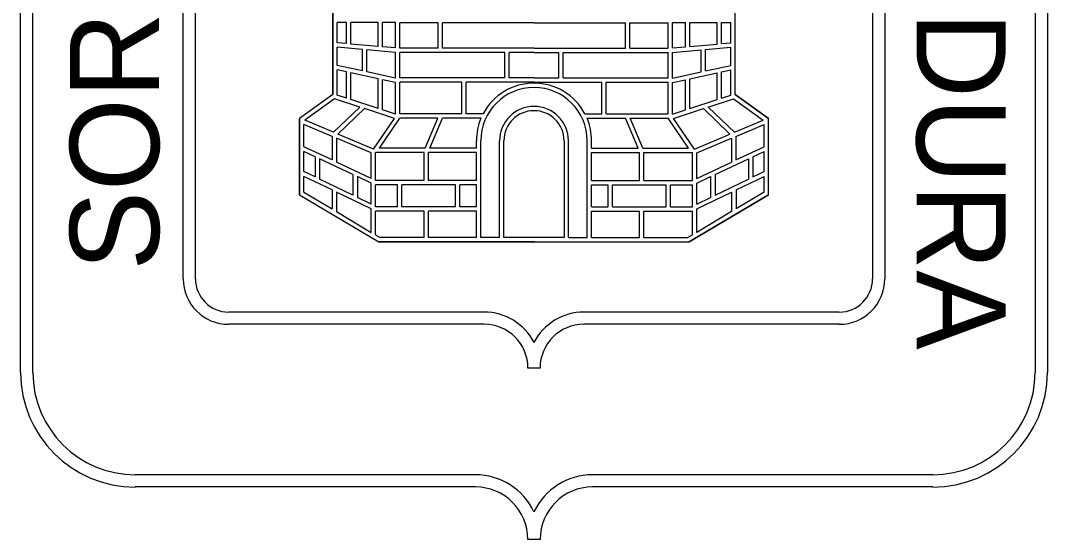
# Model space of a CAD drawing. Extents: x 0.2 to 61.3, y -17.9 to -0.8.
# Drawn here: x 50 to 60, y -17.88 to -12.82 of the extents above; entities that cross this region are included whole.
import ezdxf

# ---------------------------------------------------------------- set-up
doc = ezdxf.new("R2010")
doc.units = 0
doc.layers.add('Nivel 1', color=7, linetype='Continuous')
doc.layers.add('texto', color=7, linetype='Continuous')

msp = doc.modelspace()

# ---------------------------------------------------------------- linework, layer by layer
at = {"layer": 'Nivel 1'}
for p, q in [((50.003, -16.25), (50.003, -5.551)), ((60.003, -5.551), (60.003, -16.25)), ((50.122, -16.25), (50.122, -5.67)), ((59.884, -5.67), (59.884, -16.25)), ((51.587, -15.338), (51.587, -7.135)), ((58.419, -7.135), (58.419, -15.338)), ((51.706, -15.338), (51.706, -7.254)), ((58.3, -7.254), (58.3, -15.338)), ((53.044, -13.544), (53.044, -11.965)), ((56.962, -13.544), (56.962, -11.965)), ((53.178, -12.844), (53.087, -12.844)), ((53.087, -13.04), (53.087, -12.844)), ((53.178, -13.048), (53.178, -12.844)), ((53.485, -12.844), (53.22, -12.844)), ((53.22, -13.052), (53.22, -12.844)), ((53.485, -13.075), (53.485, -12.844)), ((53.655, -12.844), (53.528, -12.844)), ((53.528, -13.079), (53.528, -12.844)), ((53.655, -13.09), (53.655, -12.844)), ((54.07, -12.846), (53.697, -12.846)), ((53.697, -13.093), (53.697, -12.846)), ((54.07, -13.093), (54.07, -12.846)), ((55.003, -12.846), (54.113, -12.846)), ((54.113, -13.093), (54.113, -12.846)), ((55.003, -12.846), (55.893, -12.846)), ((55.893, -13.093), (55.893, -12.846)), ((55.935, -12.846), (56.309, -12.846)), ((55.935, -13.093), (55.935, -12.846)), ((56.309, -13.093), (56.309, -12.846)), ((56.351, -13.09), (56.351, -12.844)), ((56.351, -12.844), (56.478, -12.844)), ((56.478, -13.079), (56.478, -12.844)), ((56.521, -13.075), (56.521, -12.844)), ((56.521, -12.844), (56.785, -12.844)), ((56.785, -13.052), (56.785, -12.844)), ((56.828, -12.844), (56.919, -12.844)), ((56.828, -13.048), (56.828, -12.844)), ((56.919, -13.04), (56.919, -12.844)), ((53.178, -13.048), (53.087, -13.04)), ((53.087, -13.26), (53.087, -13.082)), ((53.334, -13.104), (53.087, -13.082)), ((53.485, -13.075), (53.22, -13.052)), ((53.655, -13.09), (53.528, -13.079)), ((54.07, -13.093), (53.697, -13.093)), ((55.003, -13.093), (54.113, -13.093)), ((55.003, -13.093), (55.893, -13.093)), ((55.935, -13.093), (56.309, -13.093)), ((56.351, -13.09), (56.478, -13.079)), ((56.521, -13.075), (56.785, -13.052)), ((56.672, -13.104), (56.919, -13.082)), ((56.828, -13.048), (56.919, -13.04)), ((56.919, -13.26), (56.919, -13.082)), ((53.334, -13.314), (53.334, -13.104)), ((53.376, -13.323), (53.376, -13.108)), ((53.655, -13.133), (53.376, -13.108)), ((53.655, -13.384), (53.655, -13.133)), ((54.719, -13.136), (53.697, -13.136)), ((53.697, -13.38), (53.697, -13.136)), ((54.719, -13.38), (54.719, -13.136)), ((55.003, -13.136), (54.761, -13.136)), ((54.761, -13.38), (54.761, -13.136)), ((55.003, -13.136), (55.245, -13.136)), ((55.245, -13.38), (55.245, -13.136)), ((55.287, -13.136), (56.309, -13.136)), ((55.287, -13.38), (55.287, -13.136)), ((56.309, -13.38), (56.309, -13.136)), ((56.351, -13.133), (56.63, -13.108)), ((56.351, -13.384), (56.351, -13.133)), ((56.63, -13.323), (56.63, -13.108)), ((56.672, -13.314), (56.672, -13.104)), ((53.334, -13.314), (53.087, -13.26)), ((56.672, -13.314), (56.919, -13.26)), ((53.178, -13.324), (53.087, -13.304)), ((53.087, -13.549), (53.087, -13.304)), ((53.178, -13.579), (53.178, -13.324)), ((53.485, -13.391), (53.22, -13.333)), ((53.22, -13.593), (53.22, -13.333)), ((53.655, -13.384), (53.376, -13.323)), ((53.485, -13.68), (53.485, -13.391)), ((53.655, -13.427), (53.528, -13.4)), ((53.528, -13.694), (53.528, -13.4)), ((54.719, -13.38), (53.697, -13.38)), ((55.003, -13.38), (54.761, -13.38)), ((55.003, -13.38), (55.245, -13.38)), ((55.287, -13.38), (56.309, -13.38)), ((56.351, -13.384), (56.63, -13.323)), ((56.351, -13.427), (56.478, -13.4)), ((56.478, -13.694), (56.478, -13.4)), ((56.521, -13.391), (56.785, -13.333)), ((56.521, -13.68), (56.521, -13.391)), ((56.785, -13.593), (56.785, -13.333)), ((56.828, -13.324), (56.919, -13.304)), ((56.828, -13.579), (56.828, -13.324)), ((56.919, -13.549), (56.919, -13.304)), ((53.655, -13.736), (53.655, -13.427)), ((54.3, -13.422), (53.697, -13.422)), ((53.697, -13.732), (53.697, -13.422)), ((54.3, -13.732), (54.3, -13.422)), ((55.003, -13.422), (54.343, -13.422)), ((54.343, -13.732), (54.343, -13.422)), ((55.003, -13.422), (55.663, -13.422)), ((55.663, -13.732), (55.663, -13.422)), ((55.706, -13.422), (56.309, -13.422)), ((55.706, -13.732), (55.706, -13.422)), ((56.309, -13.732), (56.309, -13.422)), ((56.351, -13.736), (56.351, -13.427)), ((53.044, -13.544), (52.72, -13.778)), ((53.06, -13.585), (52.771, -13.793)), ((53.306, -13.666), (53.06, -13.585)), ((53.178, -13.579), (53.087, -13.549)), ((53.485, -13.68), (53.22, -13.593)), ((56.521, -13.68), (56.785, -13.593)), ((56.699, -13.666), (56.946, -13.585)), ((56.828, -13.579), (56.919, -13.549)), ((56.946, -13.585), (57.234, -13.793)), ((56.962, -13.544), (57.285, -13.778)), ((53.052, -13.911), (53.306, -13.666)), ((53.094, -13.929), (53.352, -13.681)), ((53.644, -13.777), (53.352, -13.681)), ((53.655, -13.736), (53.528, -13.694)), ((56.351, -13.736), (56.478, -13.694)), ((56.362, -13.777), (56.654, -13.681)), ((56.911, -13.929), (56.654, -13.681)), ((56.954, -13.911), (56.699, -13.666)), ((52.72, -14.519), (52.72, -13.778)), ((53.052, -13.911), (52.771, -13.793)), ((53.441, -14.075), (53.644, -13.777)), ((53.498, -14.066), (53.697, -13.775)), ((54.3, -13.732), (53.697, -13.732)), ((54.065, -13.775), (53.697, -13.775)), ((53.942, -14.066), (54.065, -13.775)), ((53.988, -14.066), (54.111, -13.775)), ((54.487, -13.775), (54.111, -13.775)), ((54.507, -13.732), (54.343, -13.732)), ((55.499, -13.732), (55.663, -13.732)), ((55.519, -13.775), (55.895, -13.775)), ((55.706, -13.732), (56.309, -13.732)), ((56.018, -14.066), (55.895, -13.775)), ((56.064, -14.066), (55.941, -13.775)), ((55.941, -13.775), (56.308, -13.775)), ((56.508, -14.066), (56.308, -13.775)), ((56.565, -14.075), (56.362, -13.777)), ((56.954, -13.911), (57.234, -13.793)), ((57.285, -14.519), (57.285, -13.778)), ((52.763, -14.052), (52.763, -13.836)), ((53.038, -13.952), (52.763, -13.836)), ((56.968, -13.952), (57.243, -13.836)), ((57.243, -14.052), (57.243, -13.836)), ((53.038, -13.952), (53.038, -14.181)), ((53.081, -13.969), (53.081, -14.201)), ((53.418, -14.111), (53.081, -13.969)), ((53.441, -14.075), (53.094, -13.929)), ((54.442, -14.066), (54.442, -13.994)), ((54.485, -14.937), (54.485, -13.994)), ((54.668, -14.937), (54.668, -13.994)), ((55.338, -14.937), (55.338, -13.994)), ((55.521, -14.937), (55.521, -13.994)), ((55.564, -14.066), (55.564, -13.994)), ((56.565, -14.075), (56.911, -13.929)), ((56.588, -14.111), (56.925, -13.969)), ((56.925, -13.969), (56.925, -14.201)), ((56.968, -13.952), (56.968, -14.181)), ((53.038, -14.181), (52.763, -14.052)), ((52.763, -14.294), (52.763, -14.1)), ((52.872, -14.151), (52.763, -14.1)), ((53.942, -14.066), (53.498, -14.066)), ((54.442, -14.066), (53.988, -14.066)), ((55.564, -14.066), (56.018, -14.066)), ((56.064, -14.066), (56.508, -14.066)), ((56.968, -14.181), (57.243, -14.052)), ((57.134, -14.151), (57.243, -14.1)), ((57.243, -14.294), (57.243, -14.1)), ((52.872, -14.151), (52.872, -14.346)), ((52.915, -14.171), (52.915, -14.367)), ((53.24, -14.323), (52.915, -14.171)), ((53.418, -14.36), (53.418, -14.111)), ((53.934, -14.109), (53.461, -14.109)), ((53.461, -14.38), (53.461, -14.109)), ((53.934, -14.38), (53.934, -14.109)), ((54.442, -14.109), (53.977, -14.109)), ((53.977, -14.38), (53.977, -14.109)), ((54.442, -14.38), (54.442, -14.109)), ((55.564, -14.109), (56.029, -14.109)), ((55.564, -14.38), (55.564, -14.109)), ((56.029, -14.38), (56.029, -14.109)), ((56.071, -14.109), (56.545, -14.109)), ((56.071, -14.38), (56.071, -14.109)), ((56.545, -14.38), (56.545, -14.109)), ((56.588, -14.36), (56.588, -14.111)), ((56.766, -14.323), (57.091, -14.171)), ((57.091, -14.171), (57.091, -14.367)), ((57.134, -14.151), (57.134, -14.346)), ((52.872, -14.346), (52.763, -14.294)), ((53.418, -14.36), (53.081, -14.201)), ((56.588, -14.36), (56.925, -14.201)), ((57.134, -14.346), (57.243, -14.294)), ((52.763, -14.495), (52.763, -14.341)), ((53.036, -14.473), (52.763, -14.341)), ((53.24, -14.524), (52.915, -14.367)), ((53.24, -14.323), (53.24, -14.524)), ((53.283, -14.343), (53.283, -14.545)), ((53.418, -14.407), (53.283, -14.343)), ((53.934, -14.38), (53.461, -14.38)), ((54.442, -14.38), (53.977, -14.38)), ((55.564, -14.38), (56.029, -14.38)), ((56.071, -14.38), (56.545, -14.38)), ((56.588, -14.407), (56.723, -14.343)), ((56.723, -14.343), (56.723, -14.545)), ((56.766, -14.323), (56.766, -14.524)), ((56.766, -14.524), (57.091, -14.367)), ((56.97, -14.473), (57.243, -14.341)), ((57.243, -14.495), (57.243, -14.341)), ((52.763, -14.495), (53.036, -14.658)), ((53.036, -14.473), (53.036, -14.658)), ((53.079, -14.494), (53.079, -14.683)), ((53.418, -14.658), (53.079, -14.494)), ((53.418, -14.61), (53.418, -14.407)), ((53.674, -14.422), (53.461, -14.422)), ((53.461, -14.636), (53.461, -14.422)), ((53.674, -14.636), (53.674, -14.422)), ((53.717, -14.636), (53.717, -14.422)), ((54.237, -14.422), (53.717, -14.422)), ((54.237, -14.636), (54.237, -14.422)), ((54.28, -14.636), (54.28, -14.422)), ((54.442, -14.422), (54.28, -14.422)), ((54.442, -14.636), (54.442, -14.422)), ((55.564, -14.636), (55.564, -14.422)), ((55.564, -14.422), (55.726, -14.422)), ((55.726, -14.636), (55.726, -14.422)), ((55.768, -14.636), (55.768, -14.422)), ((55.768, -14.422), (56.289, -14.422)), ((56.289, -14.636), (56.289, -14.422)), ((56.332, -14.636), (56.332, -14.422)), ((56.332, -14.422), (56.545, -14.422)), ((56.545, -14.636), (56.545, -14.422)), ((56.588, -14.61), (56.588, -14.407)), ((56.588, -14.658), (56.927, -14.494)), ((56.927, -14.494), (56.927, -14.683)), ((56.97, -14.473), (56.97, -14.658)), ((57.243, -14.495), (56.97, -14.658)), ((52.72, -14.519), (53.492, -14.979)), ((53.418, -14.61), (53.283, -14.545)), ((57.285, -14.519), (56.514, -14.979)), ((56.588, -14.61), (56.723, -14.545)), ((53.079, -14.683), (53.418, -14.886)), ((53.418, -14.886), (53.418, -14.658)), ((53.674, -14.636), (53.461, -14.636)), ((53.934, -14.678), (53.461, -14.678)), ((53.461, -14.911), (53.461, -14.678)), ((54.237, -14.636), (53.717, -14.636)), ((53.934, -14.937), (53.934, -14.678)), ((54.442, -14.678), (53.977, -14.678)), ((53.977, -14.937), (53.977, -14.678)), ((54.442, -14.636), (54.28, -14.636)), ((54.442, -14.937), (54.442, -14.678)), ((55.564, -14.636), (55.726, -14.636)), ((55.564, -14.937), (55.564, -14.678)), ((55.564, -14.678), (56.029, -14.678)), ((55.768, -14.636), (56.289, -14.636)), ((56.029, -14.937), (56.029, -14.678)), ((56.071, -14.678), (56.545, -14.678)), ((56.071, -14.937), (56.071, -14.678)), ((56.332, -14.636), (56.545, -14.636)), ((56.545, -14.911), (56.545, -14.678)), ((56.588, -14.886), (56.588, -14.658)), ((56.927, -14.683), (56.588, -14.886)), ((53.461, -14.911), (53.504, -14.937)), ((55.003, -14.979), (53.492, -14.979)), ((53.934, -14.937), (53.504, -14.937)), ((54.442, -14.937), (53.977, -14.937)), ((54.668, -14.937), (54.485, -14.937)), ((55.003, -14.979), (56.514, -14.979)), ((55.338, -14.937), (55.521, -14.937)), ((55.564, -14.937), (56.029, -14.937)), ((56.071, -14.937), (56.502, -14.937)), ((56.545, -14.911), (56.502, -14.937)), ((54.518, -15.662), (52.03, -15.662)), ((57.976, -15.662), (55.488, -15.662)), ((54.518, -15.781), (52.03, -15.781)), ((57.976, -15.781), (55.488, -15.781)), ((55.003, -16.207), (54.943, -16.207)), ((55.063, -16.207), (55.003, -16.207)), ((54.432, -17.246), (51.119, -17.246)), ((58.887, -17.246), (55.573, -17.246)), ((54.432, -17.365), (51.119, -17.365)), ((58.887, -17.365), (55.573, -17.365)), ((55.003, -17.876), (54.943, -17.876)), ((55.063, -17.876), (55.003, -17.876))]:
    msp.add_line(p, q, dxfattribs=at)
for centre, radius, start, end in [((55.003, -13.994), 0.518, 90, 180), ((55.003, -13.994), 0.561, 90, 152.1822), ((55.003, -13.994), 0.561, 27.8178, 90), ((55.003, -13.994), 0.518, 0, 90), ((55.003, -13.994), 0.335, 90, 180), ((55.003, -13.994), 0.335, 0, 90), ((55.003, -13.994), 0.561, 157.0009, 180), ((55.003, -13.994), 0.561, 0, 22.9991), ((52.03, -15.338), 0.443, 180, 270), ((52.03, -15.338), 0.324, 180, 270), ((57.976, -15.338), 0.443, 270, 0), ((57.976, -15.338), 0.324, 270, 0), ((54.518, -16.207), 0.545, 27.0481, 90), ((55.488, -16.207), 0.545, 90, 152.9519), ((54.518, -16.207), 0.426, 0, 90), ((55.488, -16.207), 0.426, 90, 180), ((51.119, -16.25), 1.116, 180, 270), ((51.119, -16.25), 0.996, 180, 270), ((58.887, -16.25), 1.116, 270, 0), ((58.887, -16.25), 0.996, 270, 0), ((54.432, -17.876), 0.63, 25.1221, 90), ((55.573, -17.876), 0.63, 90, 154.8779), ((54.432, -17.876), 0.511, 0, 90), ((55.573, -17.876), 0.511, 90, 180)]:
    msp.add_arc(centre, radius, start, end, dxfattribs=at)
at = {"layer": 'texto'}
for p, q in [((53.044, -11.965), (53.044, -13.544)), ((56.962, -13.544), (56.962, -11.965)), ((53.044, -13.544), (52.72, -13.778)), ((57.285, -13.778), (56.962, -13.544)), ((52.72, -13.778), (52.72, -14.519)), ((57.285, -14.519), (57.285, -13.778)), ((54.71, -14.937), (54.71, -13.994)), ((55.296, -13.994), (55.296, -14.937)), ((52.72, -14.519), (53.492, -14.979)), ((56.514, -14.979), (57.285, -14.519)), ((53.492, -14.979), (55.003, -14.979)), ((55.003, -14.937), (54.71, -14.937)), ((55.296, -14.937), (55.003, -14.937)), ((55.003, -14.979), (56.514, -14.979))]:
    msp.add_line(p, q, dxfattribs=at)
for start, end in [(90, 180), (0, 90)]:
    msp.add_arc((55.003, -13.994), 0.293, start, end, dxfattribs=at)

# ---------------------------------------------------------------- texts
at = {"layer": 'Nivel 1'}
for s, height, rotation, p in [('ESTREMADURA ', 0.86862, 270, (58.728, -7.123)), ('SORIA', 0.8686, 90, (51.352, -15.258))]:
    msp.add_text(s, height=height, rotation=rotation, dxfattribs=at).set_placement(p)

doc.saveas('drawing.dxf')
